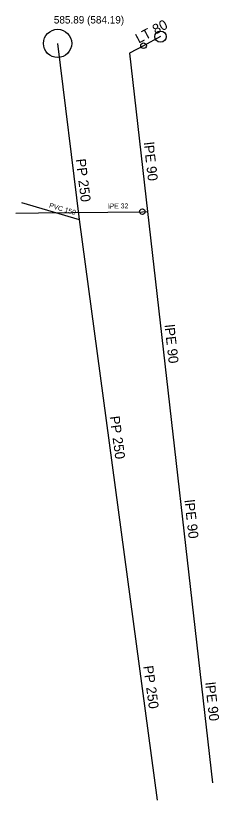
# Model space of a CAD drawing. Extents: x -673070 to -670934, y -1130499 to -1130016.
# Drawn here: x -673069.83 to -673066.23, y -1130499.1 to -1130485.2 of the extents above; entities that cross this region are included whole.
import ezdxf

# ---------------------------------------------------------------- set-up
doc = ezdxf.new("R2010")
doc.units = 0
for name, color, linetype in [('hydrant_o', 7, 'Continuous'), ('JEDN', 7, 'Continuous'), ('k_sachta_clip_Layer', 7, 'Continuous'), ('k_sachta_clip_LayerAnotace', 7, 'Continuous'), ('k_sachta_o', 7, 'Continuous'), ('kanal_clip_LayerAnotace', 7, 'Continuous'), ('soupe_o', 7, 'Continuous'), ('VOD', 7, 'Continuous'), ('vodovod_clip_LayerAnotace', 7, 'Continuous')]:
    doc.layers.add(name, color=color, linetype=linetype)

msp = doc.modelspace()

# ---------------------------------------------------------------- linework, layer by layer
at = {"layer": 'hydrant_o'}
msp.add_circle((-673067.27, -1130485.57), 0.1, dxfattribs=at)
at = {"layer": 'JEDN'}
msp.add_line((-673069.73, -1130488.51), (-673068.71, -1130488.808), dxfattribs=at)
msp.add_lwpolyline([(-673069.09, -1130485.69), (-673068.71, -1130488.808), (-673067.327, -1130499.097)], dxfattribs=at)
at = {"layer": 'k_sachta_clip_Layer'}
msp.add_line((-673069.09, -1130485.69), (-673069.09, -1130485.69), dxfattribs=at)
at = {"layer": 'k_sachta_o'}
msp.add_circle((-673069.09, -1130485.69), 0.25, dxfattribs=at)
at = {"layer": 'soupe_o'}
for centre in [(-673067.57, -1130485.73), (-673067.591, -1130488.67)]:
    msp.add_circle(centre, 0.05, dxfattribs=at)
at = {"layer": 'VOD'}
for points in [[(-673067.27, -1130485.57), (-673067.57, -1130485.73), (-673067.818, -1130485.862)], [(-673067.818, -1130485.862), (-673067.499, -1130488.669), (-673066.351, -1130498.79)], [(-673069.83, -1130488.694), (-673069.43, -1130488.69), (-673067.59, -1130488.67), (-673067.499, -1130488.669)]]:
    msp.add_lwpolyline(points, dxfattribs=at)

# ---------------------------------------------------------------- texts
at = {"layer": 'k_sachta_clip_LayerAnotace'}
msp.add_text('585.89 (584.19)', height=0.13163, dxfattribs=at).set_placement((-673069.156, -1130485.337))
at = {"layer": 'kanal_clip_LayerAnotace'}
for s, height, rotation, p in [('PP 250', 0.1755, 276.9486, (-673068.769, -1130487.742)), ('PVC 150', 0.0878, 343.7139, (-673069.247, -1130488.596)), ('PP 250', 0.1755, 277.6568, (-673068.169, -1130492.3)), ('PP 250', 0.1755, 277.6568, (-673067.575, -1130496.722))]:
    msp.add_text(s, height=height, rotation=rotation, dxfattribs=at).set_placement(p)
at = {"layer": 'vodovod_clip_LayerAnotace'}
for s, height, rotation, p in [('LT 80', 0.1755, 28.0507, (-673067.655, -1130485.695)), ('lPE 90', 0.1755, 276.4733, (-673067.567, -1130487.447)), ('lPE 32', 0.0878, 0.6145, (-673068.196, -1130488.615)), ('lPE 90', 0.1755, 276.4733, (-673067.2, -1130490.679)), ('lPE 90', 0.1755, 276.4733, (-673066.848, -1130493.782)), ('lPE 90', 0.1755, 276.4733, (-673066.482, -1130497.014))]:
    msp.add_text(s, height=height, rotation=rotation, dxfattribs=at).set_placement(p)

doc.saveas('drawing.dxf')
